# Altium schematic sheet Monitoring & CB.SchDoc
size 431 x 279 mm; Date: Not shown in title block; ApprovedBy: Not shown in title block; CheckedBy: Not shown in title block; Author: Not shown in title block; CompanyName: Not shown in title block; Engineer: Not shown in title block; Organization: Not shown in title block; Address1: Not shown in title block; Address2: Not shown in title block; Address3: Not shown in title block; Address4: Not shown in title block; DocumentNumber: 1; Revision: Use project parameter SCH_Rev; SheetNumber: 2; SheetTotal: 3; PageSetup: Record=PageOptions¦CenterHorizontal=True¦CenterVertical=True¦PrintScale=1.00¦XCorrection=1.00¦YCorrection=1.00¦PrintKind=0¦BorderSize=5000000¦LeftOffset=0¦BottomOffset=0¦Orientation=2¦PaperLength=1000¦PaperWidth=1000¦Scale=100¦PaperSource=15¦PrintQuality=600¦MediaType=1¦DitherType=10¦PaperKind=Letter¦PrintScaleMode=1
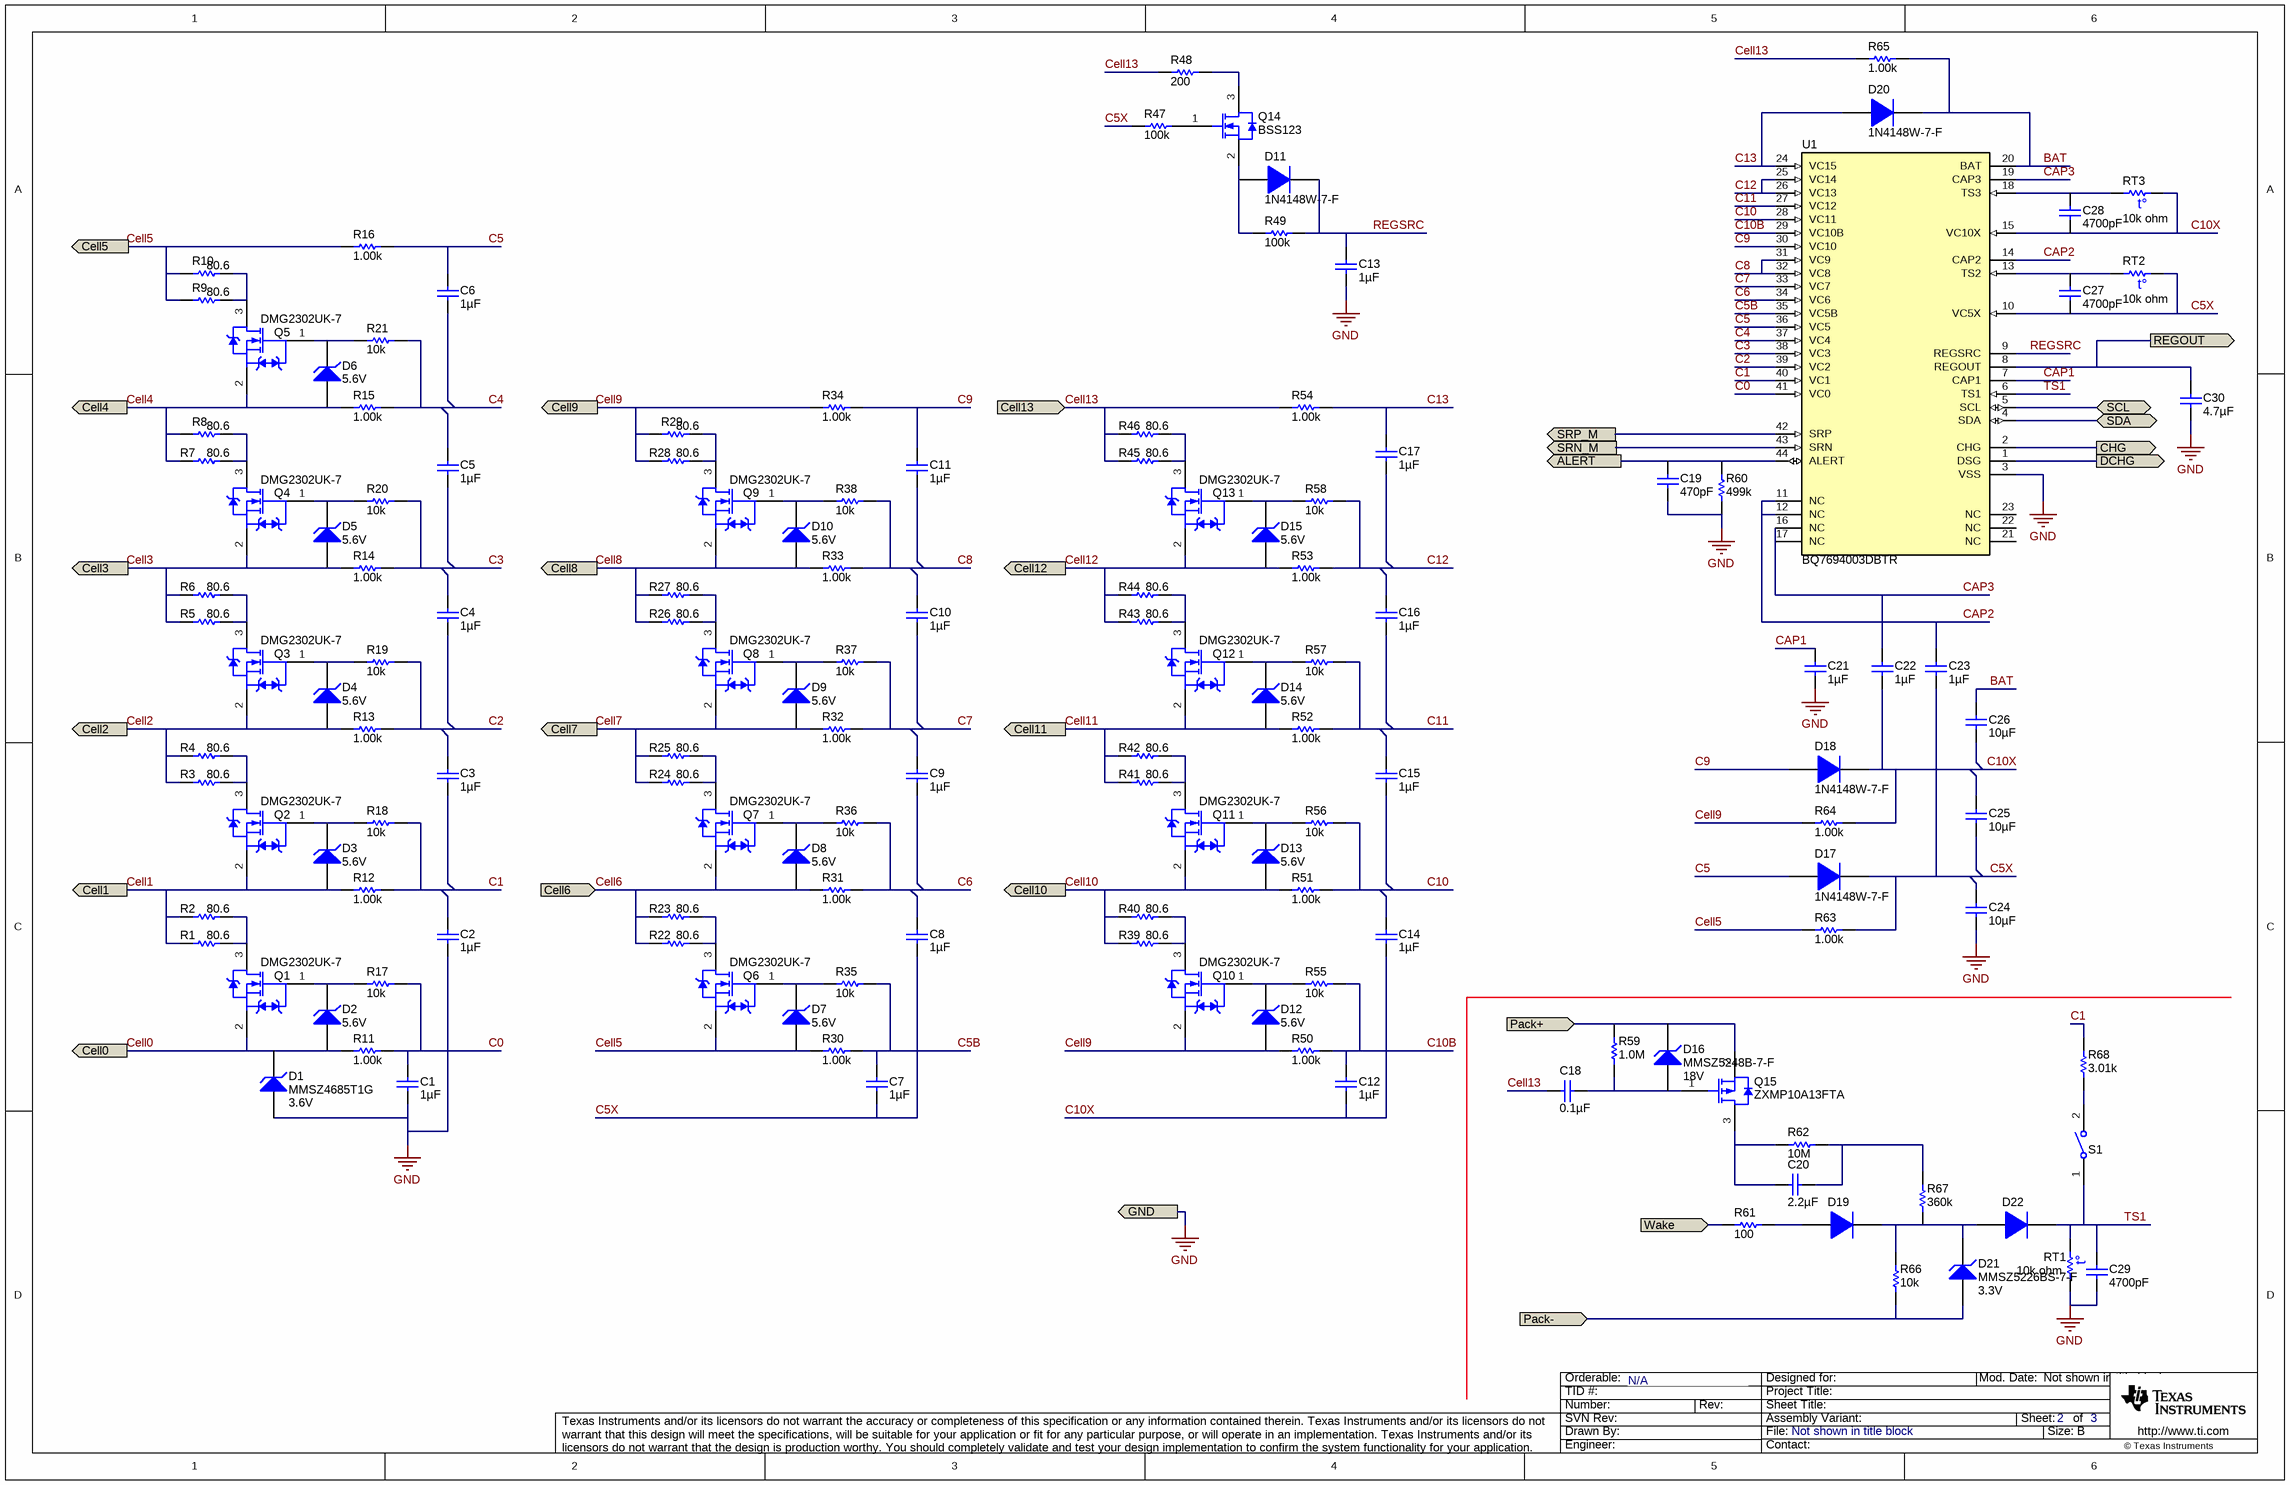
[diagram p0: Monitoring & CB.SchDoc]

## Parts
C1  ValueDisplayed: 1µF  [0603]  (hidden comment: GRM188R71C105KE15D)
C2  ValueDisplayed: 1µF  [0603S]  (hidden comment: GRM188R71C105KE15D)
C3  ValueDisplayed: 1µF  [0603]  (hidden comment: GRM188R71C105KE15D)
C4  ValueDisplayed: 1µF  [0603]  (hidden comment: GRM188R71C105KE15D)
C5  ValueDisplayed: 1µF  [0603]  (hidden comment: GRM188R71C105KE15D)
C6  ValueDisplayed: 1µF  [0603]  (hidden comment: GRM188R71C105KE15D)
C7  ValueDisplayed: 1µF  [0603S]  (hidden comment: GRM188R71C105KE15D)
C8  ValueDisplayed: 1µF  [0603S]  (hidden comment: GRM188R71C105KE15D)
C9  ValueDisplayed: 1µF  [0603]  (hidden comment: GRM188R71C105KE15D)
C10  ValueDisplayed: 1µF  [0603]  (hidden comment: GRM188R71C105KE15D)
C11  ValueDisplayed: 1µF  [0603]  (hidden comment: GRM188R71C105KE15D)
C12  ValueDisplayed: 1µF  [0603]  (hidden comment: GRM188R71C105KE15D)
C13  ValueDisplayed: 1µF  [0603S]  (hidden comment: C1608X7R1V105K080AC)
C14  ValueDisplayed: 1µF  [0603]  (hidden comment: GRM188R71C105KE15D)
C15  ValueDisplayed: 1µF  [0603]  (hidden comment: GRM188R71C105KE15D)
C16  ValueDisplayed: 1µF  [0603]  (hidden comment: GRM188R71C105KE15D)
C17  ValueDisplayed: 1µF  [0603]  (hidden comment: GRM188R71C105KE15D)
C18  ValueDisplayed: 0.1µF  [0805_HV]  (hidden comment: CGA4J2X7R2A104K125AA)
C19  ValueDisplayed: 470pF  [0603]  (hidden comment: GCM1885C1H471JA16D)
C20  ValueDisplayed: 2.2µF  [1210_270]  (hidden comment: GRM32ER72A225KA35L)
C21  ValueDisplayed: 1µF  [0603S]  (hidden comment: GRM188R71C105KE15D)
C22  ValueDisplayed: 1µF  [0603S]  (hidden comment: GRM188R71C105KE15D)
C23  ValueDisplayed: 1µF  [0603S]  (hidden comment: GRM188R71C105KE15D)
C24  ValueDisplayed: 10µF  [1210_280]  (hidden comment: C3225X5R1H106K250AB)
C25  ValueDisplayed: 10µF  [1210_280]  (hidden comment: C3225X5R1H106K250AB)
C26  ValueDisplayed: 10µF  [1210_280]  (hidden comment: C3225X5R1H106K250AB)
C27  ValueDisplayed: 4700pF  [0603S]  (hidden comment: GCM188R71H472KA37D)
C28  ValueDisplayed: 4700pF  [0603]  (hidden comment: GCM188R71H472KA37D)
C29  ValueDisplayed: 4700pF  [0603]  (hidden comment: GCM188R71H472KA37D)
C30  ValueDisplayed: 4.7µF  [0603S]  (hidden comment: GRM188R61C475KAAJ)
D1  MMSZ4685T1G  value 3.6V  [SOD-123]
D2  value 5.6V  [SOD-523]  (hidden comment: BZT52C5V6T-7)
D3  value 5.6V  [SOD-523]  (hidden comment: BZT52C5V6T-7)
D4  value 5.6V  [SOD-523]  (hidden comment: BZT52C5V6T-7)
D5  value 5.6V  [SOD-523]  (hidden comment: BZT52C5V6T-7)
D6  value 5.6V  [SOD-523]  (hidden comment: BZT52C5V6T-7)
D7  value 5.6V  [SOD-523]  (hidden comment: BZT52C5V6T-7)
D8  value 5.6V  [SOD-523]  (hidden comment: BZT52C5V6T-7)
D9  value 5.6V  [SOD-523]  (hidden comment: BZT52C5V6T-7)
D10  value 5.6V  [SOD-523]  (hidden comment: BZT52C5V6T-7)
D11  1N4148W-7-F  [SOD-123]
D12  value 5.6V  [SOD-523]  (hidden comment: BZT52C5V6T-7)
D13  value 5.6V  [SOD-523]  (hidden comment: BZT52C5V6T-7)
D14  value 5.6V  [SOD-523]  (hidden comment: BZT52C5V6T-7)
D15  value 5.6V  [SOD-523]  (hidden comment: BZT52C5V6T-7)
D16  MMSZ5248B-7-F  value 18V  [SOD-123]
D17  1N4148W-7-F  [SOD-123]
D18  1N4148W-7-F  [SOD-123]
D19  SBR0220T5-7  [SOD-523]  (value not drawn)
D20  1N4148W-7-F  [SOD-123]
D21  MMSZ5226BS-7-F  value 3.3V  [SOD-323]
D22  SBR0220T5-7  [SOD-523]  (value not drawn)
Q1  DMG2302UK-7  [SOT-23]
Q2  DMG2302UK-7  [SOT-23]
Q3  DMG2302UK-7  [SOT-23]
Q4  DMG2302UK-7  [SOT-23]
Q5  DMG2302UK-7  [SOT-23]
Q6  DMG2302UK-7  [SOT-23]
Q7  DMG2302UK-7  [SOT-23]
Q8  DMG2302UK-7  [SOT-23]
Q9  DMG2302UK-7  [SOT-23]
Q10  DMG2302UK-7  [SOT-23]
Q11  DMG2302UK-7  [SOT-23]
Q12  DMG2302UK-7  [SOT-23]
Q13  DMG2302UK-7  [SOT-23]
Q14  BSS123  [SOT-23]
Q15  ZXMP10A13FTA  [SOT-23]
R1  ValueDisplayed: 80.6  [1206]  (hidden comment: CRCW120680R6FKEA)
R2  ValueDisplayed: 80.6  [1206]  (hidden comment: CRCW120680R6FKEA)
R3  ValueDisplayed: 80.6  [1206]  (hidden comment: CRCW120680R6FKEA)
R4  ValueDisplayed: 80.6  [1206]  (hidden comment: CRCW120680R6FKEA)
R5  ValueDisplayed: 80.6  [1206]  (hidden comment: CRCW120680R6FKEA)
R6  ValueDisplayed: 80.6  [1206]  (hidden comment: CRCW120680R6FKEA)
R7  ValueDisplayed: 80.6  [1206]  (hidden comment: CRCW120680R6FKEA)
R8  ValueDisplayed: 80.6  [1206]  (hidden comment: CRCW120680R6FKEA)
R9  ValueDisplayed: 80.6  [1206]  (hidden comment: CRCW120680R6FKEA)
R10  ValueDisplayed: 80.6  [1206]  (hidden comment: CRCW120680R6FKEA)
R11  ValueDisplayed: 1.00k  [0603]  (hidden comment: CRCW06031K00FKEA)
R12  ValueDisplayed: 1.00k  [0603]  (hidden comment: CRCW06031K00FKEA)
R13  ValueDisplayed: 1.00k  [0603]  (hidden comment: CRCW06031K00FKEA)
R14  ValueDisplayed: 1.00k  [0603]  (hidden comment: CRCW06031K00FKEA)
R15  ValueDisplayed: 1.00k  [0603]  (hidden comment: CRCW06031K00FKEA)
R16  ValueDisplayed: 1.00k  [0603]  (hidden comment: CRCW06031K00FKEA)
R17  ValueDisplayed: 10k  [0603]  (hidden comment: CRCW060310K0JNEA)
R18  ValueDisplayed: 10k  [0603]  (hidden comment: CRCW060310K0JNEA)
R19  ValueDisplayed: 10k  [0603]  (hidden comment: CRCW060310K0JNEA)
R20  ValueDisplayed: 10k  [0603]  (hidden comment: CRCW060310K0JNEA)
R21  ValueDisplayed: 10k  [0603]  (hidden comment: CRCW060310K0JNEA)
R22  ValueDisplayed: 80.6  [1206]  (hidden comment: CRCW120680R6FKEA)
R23  ValueDisplayed: 80.6  [1206]  (hidden comment: CRCW120680R6FKEA)
R24  ValueDisplayed: 80.6  [1206]  (hidden comment: CRCW120680R6FKEA)
R25  ValueDisplayed: 80.6  [1206]  (hidden comment: CRCW120680R6FKEA)
R26  ValueDisplayed: 80.6  [1206]  (hidden comment: CRCW120680R6FKEA)
R27  ValueDisplayed: 80.6  [1206]  (hidden comment: CRCW120680R6FKEA)
R28  ValueDisplayed: 80.6  [1206]  (hidden comment: CRCW120680R6FKEA)
R29  ValueDisplayed: 80.6  [1206]  (hidden comment: CRCW120680R6FKEA)
R30  ValueDisplayed: 1.00k  [0603]  (hidden comment: CRCW06031K00FKEA)
R31  ValueDisplayed: 1.00k  [0603]  (hidden comment: CRCW06031K00FKEA)
R32  ValueDisplayed: 1.00k  [0603]  (hidden comment: CRCW06031K00FKEA)
R33  ValueDisplayed: 1.00k  [0603]  (hidden comment: CRCW06031K00FKEA)
R34  ValueDisplayed: 1.00k  [0603]  (hidden comment: CRCW06031K00FKEA)
R35  ValueDisplayed: 10k  [0603]  (hidden comment: CRCW060310K0JNEA)
R36  ValueDisplayed: 10k  [0603]  (hidden comment: CRCW060310K0JNEA)
R37  ValueDisplayed: 10k  [0603]  (hidden comment: CRCW060310K0JNEA)
R38  ValueDisplayed: 10k  [0603]  (hidden comment: CRCW060310K0JNEA)
R39  ValueDisplayed: 80.6  [1206]  (hidden comment: CRCW120680R6FKEA)
R40  ValueDisplayed: 80.6  [1206]  (hidden comment: CRCW120680R6FKEA)
R41  ValueDisplayed: 80.6  [1206]  (hidden comment: CRCW120680R6FKEA)
R42  ValueDisplayed: 80.6  [1206]  (hidden comment: CRCW120680R6FKEA)
R43  ValueDisplayed: 80.6  [1206]  (hidden comment: CRCW120680R6FKEA)
R44  ValueDisplayed: 80.6  [1206]  (hidden comment: CRCW120680R6FKEA)
R45  ValueDisplayed: 80.6  [1206]  (hidden comment: CRCW120680R6FKEA)
R46  ValueDisplayed: 80.6  [1206]  (hidden comment: CRCW120680R6FKEA)
R47  ValueDisplayed: 100k  [0603]  (hidden comment: CRCW0603100KFKEA)
R48  ValueDisplayed: 200  [0603]  (hidden comment: CRCW0603200RFKEA)
R49  ValueDisplayed: 100k  [0603]  (hidden comment: CRCW0603100KFKEA)
R50  ValueDisplayed: 1.00k  [0603]  (hidden comment: CRCW06031K00FKEA)
R51  ValueDisplayed: 1.00k  [0603]  (hidden comment: CRCW06031K00FKEA)
R52  ValueDisplayed: 1.00k  [0603]  (hidden comment: CRCW06031K00FKEA)
R53  ValueDisplayed: 1.00k  [0603]  (hidden comment: CRCW06031K00FKEA)
R54  ValueDisplayed: 1.00k  [0603]  (hidden comment: CRCW06031K00FKEA)
R55  ValueDisplayed: 10k  [0603]  (hidden comment: CRCW060310K0JNEA)
R56  ValueDisplayed: 10k  [0603]  (hidden comment: CRCW060310K0JNEA)
R57  ValueDisplayed: 10k  [0603]  (hidden comment: CRCW060310K0JNEA)
R58  ValueDisplayed: 10k  [0603]  (hidden comment: CRCW060310K0JNEA)
R59  ValueDisplayed: 1.0M  [0603]  (hidden comment: CRCW06031M00JNEA)
R60  ValueDisplayed: 499k  [0603]  (hidden comment: CRCW0603499KFKEA)
R61  ValueDisplayed: 100  [0603]  (hidden comment: CRCW0603100RFKEA)
R62  ValueDisplayed: 10M  [0603]  (hidden comment: CRCW060310M0JNEA)
R63  ValueDisplayed: 1.00k  [0603]  (hidden comment: CRCW06031K00FKEA)
R64  ValueDisplayed: 1.00k  [0603]  (hidden comment: CRCW06031K00FKEA)
R65  ValueDisplayed: 1.00k  [0603]  (hidden comment: CRCW06031K00FKEA)
R66  ValueDisplayed: 10k  [0603]  (hidden comment: CRCW060310K0JNEA)
R67  ValueDisplayed: 360k  [0603]  (hidden comment: ERJ-3EKF3603V)
R68  ValueDisplayed: 3.01k  [0603S]  (hidden comment: CRCW06033K01FKEA)
RT1  value 10k ohm  [NTCALUG03]  (hidden comment: NTCALUG03A103G)
RT2  value 10k ohm  [NTCALUG03]  (hidden comment: NTCALUG03A103G)
RT3  value 10k ohm  [NTCALUG03]  (hidden comment: NTCALUG03A103G)
S1  RS-032G05A3-SM RT  [SW_RS-032G05A3-SM]  (value not drawn)
U1  BQ7694003DBTR  [DBT0044A_N]

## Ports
ALERT (out), Cell0 (in), Cell1 (in), Cell2 (in), Cell3 (in), Cell4 (in), Cell5 (in), Cell6 (in), Cell7 (in), Cell8 (in), Cell9 (in), Cell10 (in), Cell11 (in), Cell12 (in), Cell13 (in), CHG (out), DCHG (out), GND, Pack+ (in), Pack- (in), REGOUT (out), SCL (bidir), SDA (bidir), SRN_M (in), SRP_M (in), Wake (in)

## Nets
GND: C1.2 C2.2 C13.2 C19.2 C21.2 C24.1 C29.2 C30.2 D1.2(A) R60.1 RT1.1 U1.3(VSS) ; port GND
ALERT: C19.1 R60.2 U1.44(ALERT) ; port ALERT
BAT: C26.2 D20.1(K) R65.2 U1.20(BAT)
C0: C1.1 R11.2 R17.2 U1.41(VC0)
C1: C2.1 C3.2 R12.2 R18.2 R68.2 U1.40(VC1)
C2: C3.1 C4.2 R13.2 R19.2 U1.39(VC2)
C3: C4.1 C5.2 R14.2 R20.2 U1.38(VC3)
C4: C5.1 C6.2 R15.2 R21.2 U1.37(VC4)
C5: C6.1 D17.2(A) R16.2 U1.36(VC5)
C5B: C7.1 R30.2 R35.2 U1.35(VC5B)
C5X: C7.2 C8.2 C23.2 C24.2 C25.1 C27.2 D17.1(K) R47.1 R63.2 RT2.2 U1.10(VC5X)
C6: C8.1 C9.2 R31.2 R36.2 U1.34(VC6)
C7: C9.1 C10.2 R32.2 R37.2 U1.33(VC7)
C8: C10.1 C11.2 R33.2 R38.2 U1.31(VC9) U1.32(VC8)
C9: C11.1 D18.2(A) R34.2 U1.30(VC10)
C10: C14.1 C15.2 R51.2 R56.2 U1.28(VC11)
C10B: C12.1 R50.2 R55.2 U1.29(VC10B)
C10X: C12.2 C14.2 C22.2 C25.2 C26.1 C28.2 D18.1(K) R64.2 RT3.2 U1.15(VC10X)
C11: C15.1 C16.2 R52.2 R57.2 U1.27(VC12)
C12: C16.1 C17.2 R53.2 R58.2 U1.25(VC14) U1.26(VC13)
C13: C17.1 D20.2(A) R54.2 U1.24(VC15)
CAP1: C21.1 U1.7(CAP1)
CAP2: C23.1 U1.11(NC) U1.12(NC) U1.14(CAP2)
CAP3: C22.1 U1.16(NC) U1.17(NC) U1.19(CAP3)
Cell0: D1.1(K) D2.2(A) Q1.2(S) R11.1 ; port Cell0
Cell1: D3.2(A) Q2.2(S) R1.2 R2.2 R12.1 ; port Cell1
Cell2: D4.2(A) Q3.2(S) R3.2 R4.2 R13.1 ; port Cell2
Cell3: D5.2(A) Q4.2(S) R5.2 R6.2 R14.1 ; port Cell3
Cell4: D6.2(A) Q5.2(S) R7.2 R8.2 R15.1 ; port Cell4
Cell5: D7.2(A) Q6.2(S) R9.2 R10.2 R16.1 R30.1 R63.1 ; port Cell5
Cell6: D8.2(A) Q7.2(S) R22.2 R23.2 R31.1 ; port Cell6
Cell7: D9.2(A) Q8.2(S) R24.2 R25.2 R32.1 ; port Cell7
Cell8: D10.2(A) Q9.2(S) R26.2 R27.2 R33.1 ; port Cell8
Cell9: D12.2(A) Q10.2(S) R28.2 R29.2 R34.1 R50.1 R64.1 ; port Cell9
Cell10: D13.2(A) Q11.2(S) R39.2 R40.2 R51.1 ; port Cell10
Cell11: D14.2(A) Q12.2(S) R41.2 R42.2 R52.1 ; port Cell11
Cell12: D15.2(A) Q13.2(S) R43.2 R44.2 R53.1 ; port Cell12
Cell13: C18.2 R45.2 R46.2 R48.1 R54.1 R65.1 ; port Cell13
CHG: U1.2(CHG) ; port CHG
DCHG: U1.1(DSG) ; port DCHG
Pack+: D16.1(K) Q15.2(S) R59.2 ; port Pack+
Pack-: D21.2(A) R66.1 ; port Pack-
REGOUT: C30.1 U1.8(REGOUT) ; port REGOUT
REGSRC: C13.1 D11.1(K) R49.2 U1.9(REGSRC)
SCL: U1.5(SCL) ; port SCL
SDA: U1.4(SDA) ; port SDA
SRN_M: U1.43(SRN) ; port SRN_M
SRP_M: U1.42(SRP) ; port SRP_M
TS1: C29.1 D22.1(K) RT1.2 S1.1 U1.6(TS1)
Wake: R61.2 ; port Wake
NetC18_1: C18.1 D16.2(A) Q15.1(G) R59.1
NetC20_1: C20.1 R62.2 R67.2
NetC20_2: C20.2 Q15.3(D) R62.1
NetC27_1: C27.1 RT2.1 U1.13(TS2)
NetC28_1: C28.1 RT3.1 U1.18(TS3)
NetD2_1: D2.1(K) Q1.1(G) R17.1
NetD3_1: D3.1(K) Q2.1(G) R18.1
NetD4_1: D4.1(K) Q3.1(G) R19.1
NetD5_1: D5.1(K) Q4.1(G) R20.1
NetD6_1: D6.1(K) Q5.1(G) R21.1
NetD7_1: D7.1(K) Q6.1(G) R35.1
NetD8_1: D8.1(K) Q7.1(G) R36.1
NetD9_1: D9.1(K) Q8.1(G) R37.1
NetD10_1: D10.1(K) Q9.1(G) R38.1
NetD11_2: D11.2(A) Q14.2(S) R49.1
NetD12_1: D12.1(K) Q10.1(G) R55.1
NetD13_1: D13.1(K) Q11.1(G) R56.1
NetD14_1: D14.1(K) Q12.1(G) R57.1
NetD15_1: D15.1(K) Q13.1(G) R58.1
NetD19_1: D19.1(K) D21.1(K) D22.2(A) R66.2 R67.1
NetD19_2: D19.2(A) R61.1
NetQ1_3: Q1.3(D) R1.1 R2.1
NetQ2_3: Q2.3(D) R3.1 R4.1
NetQ3_3: Q3.3(D) R5.1 R6.1
NetQ4_3: Q4.3(D) R7.1 R8.1
NetQ5_3: Q5.3(D) R9.1 R10.1
NetQ6_3: Q6.3(D) R22.1 R23.1
NetQ7_3: Q7.3(D) R24.1 R25.1
NetQ8_3: Q8.3(D) R26.1 R27.1
NetQ9_3: Q9.3(D) R28.1 R29.1
NetQ10_3: Q10.3(D) R39.1 R40.1
NetQ11_3: Q11.3(D) R41.1 R42.1
NetQ12_3: Q12.3(D) R43.1 R44.1
NetQ13_3: Q13.3(D) R45.1 R46.1
NetQ14_1: Q14.1(G) R47.2
NetQ14_3: Q14.3(D) R48.2
NetR68_1: R68.1 S1.2

Not connected (* = marked no-connect by the designer): U1 21(NC) 22(NC) 23(NC)

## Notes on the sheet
- N/A

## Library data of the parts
C1 C3-C6 C9-C12 C14-C17 = GRM188R71C105KE15D: CAP, CERM, 1 µF, 16 V,+/- 10%, X7R, 0603; Manufacturer: MuRata; Polarized: N; CompType: Capacitor; Value: 1uF; U/M: EA; Cap_F: 0.000001; Tolerance_%: 10; VDC_V: 16; Value2: 16V; TaMin_C: -55; TaMax_C: 125; SizeArea_mm2: 1.28; SizeAreaWB_mm2: 4.68; SizeX_mm: 1.6; SizeY_mm: 0.8; SizeZ_mm: 1; AEC Category: Q200
C2 C7 C8 C21-C23 = GRM188R71C105KE15D: CAP, CERM, 1 µF, 16 V,+/- 10%, X7R, 0603; Manufacturer: MuRata; Polarized: N; CompType: Capacitor; Value: 1uF; U/M: EA; Cap_F: 0.000001; Tolerance_%: 10; VDC_V: 16; Value2: 16V; TaMin_C: -55; TaMax_C: 125; Cap_Case: 0603; SizeArea_mm2: 1.28; SizeAreaWB_mm2: 4.68; SizeX_mm: 1.6; SizeY_mm: 0.8; SizeZ_mm: 1; AEC Category: Q200
C13 = C1608X7R1V105K080AC: CAP, CERM, 1 µF, 35 V,+/- 10%, X7R, 0603; Manufacturer: TDK; Polarized: N; CompType: Capacitor; Value: 1uF; U/M: EA; Cap_F: 0.000001; Tolerance_%: 10; VDC_V: 35; Value2: 35V; TaMin_C: -55; TaMax_C: 125; Cap_Case: 0603; SizeArea_mm2: 1.28; SizeAreaWB_mm2: 4.68; SizeX_mm: 1.6; SizeY_mm: 0.8; SizeZ_mm: 1; AEC Category: Q200; Green_Lifecycle: Active; Green_REACh: Passed
C18 = CGA4J2X7R2A104K125AA: CAP, CERM, 0.1 µF, 100 V,+/- 10%, X7R, AEC-Q200 Grade 1, 0805; Manufacturer: TDK; Polarized: N; CompType: Capacitor; Value: 0.1uF; U/M: EA; Cap_F: 0.0000001; Tolerance_%: 10; ESR_ohm: 0.020726; Value1: 0.020726 ohm; VDC_V: 100; Value2: 100V; IRMS_A: 1.456; TaMin_C: -55; TaMax_C: 125; Cap_Case: 0805; SizeArea_mm2: 2.5; SizeAreaWB_mm2: 6.75; SizeX_mm: 2; SizeY_mm: 1.25; SizeZ_mm: 1.45; AEC Category: Q200; AEC Qualified: Y; AEC Grade: 1; Green_Lifecycle: Active; Green_REACh: Passed
C19 = GCM1885C1H471JA16D: CAP, CERM, 470 pF, 50 V,+/- 5%, C0G/NP0, AEC-Q200 Grade 1, 0603; Manufacturer: MuRata; Polarized: N; CompType: Capacitor; Value: 470pF; U/M: EA; Cap_F: 0.00000000047; Tolerance_%: 5; VDC_V: 50; Value2: 50V; TaMin_C: -55; TaMax_C: 125; SizeArea_mm2: 1.28; SizeAreaWB_mm2: 4.68; SizeX_mm: 1.6; SizeY_mm: 0.8; SizeZ_mm: 1; AEC Category: Q200; AEC Qualified: Y; Green_Lifecycle: Active; Green_REACh: Passed
C20 = GRM32ER72A225KA35L: CAP, CERM, 2.2 µF, 100 V,+/- 10%, X7R, 1210; Manufacturer: MuRata; Polarized: N; CompType: Capacitor; Value: 2.2uF; U/M: EA; Cap_F: 0.0000022; Tolerance_%: 10; ESR_ohm: 0.007; Value1: 0.007 ohm; VDC_V: 100; Value2: 100V; IRMS_A: 4.4; TaMin_C: -55; TaMax_C: 125; Cap_Case: 1210; SizeArea_mm2: 8; SizeAreaWB_mm2: 14.7; SizeX_mm: 3.2; SizeY_mm: 2.5; SizeZ_mm: 2.7; AEC Category: Q200; Green_Lifecycle: Active; Green_REACh: Passed
C24-C26 = C3225X5R1H106K250AB: CAP, CERM, 10 µF, 50 V,+/- 10%, X5R, 1210; Manufacturer: TDK; Polarized: N; CompType: Capacitor; Value: 10uF; U/M: EA; Cap_F: 0.00001; Tolerance_%: 10; VDC_V: 50; Value2: 50V; TaMin_C: -55; TaMax_C: 85; Cap_Case: 1210; SizeArea_mm2: 8; SizeAreaWB_mm2: 14.7; SizeX_mm: 3.2; SizeY_mm: 2.5; SizeZ_mm: 2.8; AEC Category: Q200; Green_Lifecycle: Active; Green_REACh: Passed
C27 = GCM188R71H472KA37D: CAP, CERM, 4700 pF, 50 V,+/- 10%, X7R, AEC-Q200 Grade 1, 0603; Manufacturer: MuRata; Polarized: N; CompType: Capacitor; Value: 4700pF; U/M: EA; Cap_F: 0.0000000047; Tolerance_%: 10; VDC_V: 50; Value2: 50V; TaMin_C: -55; TaMax_C: 125; Cap_Case: 0603; SizeArea_mm2: 1.28; SizeAreaWB_mm2: 4.68; SizeX_mm: 1.6; SizeY_mm: 0.8; SizeZ_mm: 1; AEC Category: Q200; AEC Qualified: Y
C28 C29 = GCM188R71H472KA37D: CAP, CERM, 4700 pF, 50 V,+/- 10%, X7R, AEC-Q200 Grade 1, 0603; Manufacturer: MuRata; Polarized: N; CompType: Capacitor; Value: 4700pF; U/M: EA; Cap_F: 0.0000000047; Tolerance_%: 10; VDC_V: 50; Value2: 50V; TaMin_C: -55; TaMax_C: 125; SizeArea_mm2: 1.28; SizeAreaWB_mm2: 4.68; SizeX_mm: 1.6; SizeY_mm: 0.8; SizeZ_mm: 1; AEC Category: Q200; AEC Qualified: Y
C30 = GRM188R61C475KAAJ: CAP, CERM, 4.7 µF, 16 V,+/- 10%, X5R, 0603; Manufacturer: MuRata; Polarized: N; CompType: Capacitor; Value: 4.7uF; U/M: EA; Cap_F: 0.0000047; Tolerance_%: 10; VDC_V: 16; Value2: 16V; TaMin_C: -55; TaMax_C: 85; Cap_Case: 0603; SizeArea_mm2: 1.28; SizeAreaWB_mm2: 4.68; SizeX_mm: 1.6; SizeY_mm: 0.8; SizeZ_mm: 1; AEC Category: Q200; Green_Lifecycle: Active; Green_REACh: Passed
D1 = MMSZ4685T1G: Diode, Zener, 3.6 V, 500 mW, SOD-123; Manufacturer: ON Semiconductor; SymbolCreator: a0412235; U/M: EA; Power_W: 0.5; Vz_V: 3.6; Value1: 0.5W; RJA_CperW: 340; SizeAreaWB_mm2: 13.095; SizeArea_mm2: 6.545; SizeX_mm: 3.85; SizeY_mm: 1.7; SizeZ_mm: 1.35; AEC Category: Q101; Green_Lifecycle: Active; Green_REACh: Passed
D2-D10 D12-D15 = BZT52C5V6T-7: Diode, Zener, 5.6 V, 300 mW, SOD-523; Manufacturer: Diodes Inc.; SymbolCreator: a0412235; U/M: EA; Power_W: 0.3; Vz_V: 5.6; Value1: 0.3W; RJA_CperW: 417; SizeAreaWB_mm2: 5.13; SizeArea_mm2: 1.53; SizeX_mm: 1.7; SizeY_mm: 0.9; SizeZ_mm: 0.65; AEC Category: Q101; Green_Lifecycle: Active; Green_REACh: Passed
D11 D17 D18 D20 = 1N4148W-7-F: Diode, Ultrafast, 100 V, 0.15 A, SOD-123; Manufacturer: Diodes Inc.; U/M: EA; Vf_V: 1.25; Value: 100V; Value1: 0.15A; Value2: 1.25V; Io_A: 0.15; Vr_V: 100; TJmax_C: 150; SizeAreaWB_mm2: 13.095; SizeArea_mm2: 6.545; SizeX_mm: 3.85; SizeY_mm: 1.7; SizeZ_mm: 1.35; AEC Category: Q101; Green_Lifecycle: Active; Green_REACh: Passed
D16 = MMSZ5248B-7-F: Diode, Zener, 18 V, 500 mW, SOD-123; Manufacturer: Diodes Inc.; SymbolCreator: a0412235; U/M: EA; Power_W: 0.5; Vz_V: 18; Value1: 0.5W; RJA_CperW: 350; SizeAreaWB_mm2: 13.095; SizeArea_mm2: 6.545; SizeX_mm: 3.85; SizeY_mm: 1.7; SizeZ_mm: 1.35; AEC Category: Q101; Green_Lifecycle: Active; Green_REACh: Passed
D19 D22 = SBR0220T5-7: Diode, Super Barrier Rectifier, 20 V, 0.2 A, SOD-523; Manufacturer: Diodes Inc.; U/M: EA; Vf_V: 0.43; Value: 20V; Value1: 0.2A; Value2: 0.43V; Io_A: 0.2; Vr_V: 20; TJmax_C: 150; SizeAreaWB_mm2: 5.13; SizeArea_mm2: 1.53; SizeX_mm: 1.7; SizeY_mm: 0.9; SizeZ_mm: 0.65; AEC Category: Q101; Green_Lifecycle: Active; Green_REACh: Passed
D21 = MMSZ5226BS-7-F: Diode, Zener, 3.3 V, 200 mW, SOD-323; Manufacturer: Diodes Inc.; SymbolCreator: a0412235; U/M: EA; Power_W: 0.2; Vz_V: 3.3; Value1: 0.2W; RJA_CperW: 350; SizeAreaWB_mm2: 8.695; SizeArea_mm2: 3.645; SizeX_mm: 2.7; SizeY_mm: 1.35; SizeZ_mm: 1; AEC Category: Q101; Green_Lifecycle: Active; Green_REACh: Passed
Q1-Q13 = DMG2302UK-7: MOSFET, N-CH, 20 V, 2.8 A, AEC-Q101, SOT-23; Manufacturer: Diodes Inc.; Alternate Manufacturer: None; SymbolCreator: x0208325; U/M: EA; ChType: N; Value: 20V; VdsMax_V: 20; Value1: 0.09 ohm; Rdson45_ohm: 0.09; Value2: 1.4 nC; QgTyp_nC: 1.4; Vgs_V: 12; IdsMax_A: 2.8; SizeAreaWB_mm2: 14; SizeArea_mm2: 7.5; SizeX_mm: 2.5; SizeY_mm: 3; SizeZ_mm: 1.1; AEC Category: Q101; AEC Qualified: Y; Green_Lifecycle: Active; Green_REACh: Passed
Q14 = BSS123: MOSFET, N-CH, 100 V, 0.17 A, SOT-23; Manufacturer: Fairchild Semiconductor; Alternate Manufacturer: None; U/M: EA; ChType: N; Value: 100V; VdsMax_V: 100; Value1: 10 ohm; Rdson45_ohm: 10; Value2: 1.8 nC; QgTyp_nC: 1.8; Vgs_V: 20; IdsMax_A: 0.17; SizeAreaWB_mm2: 14; SizeArea_mm2: 7.5; SizeX_mm: 2.5; SizeY_mm: 3; SizeZ_mm: 1.1; AEC Category: Q101; Green_Lifecycle: Active; Green_REACh: Passed
Q15 = ZXMP10A13FTA: MOSFET, P-CH, -100 V, -0.6 A, SOT-23; Manufacturer: Diodes Inc.; Alternate Manufacturer: None; U/M: EA; ChType: P; Value: -100V; Value1: 1 ohm; Rdson45_ohm: 1; Value2: 3.5 nC; QgTyp_nC: 3.5; Vgs_V: -4; SizeAreaWB_mm2: 14; SizeArea_mm2: 7.5; SizeX_mm: 2.5; SizeY_mm: 3; SizeZ_mm: 1.1; AEC Category: Q101; Green_Lifecycle: Active; Green_REACh: Passed
R1-R10 R22-R29 R39-R46 = CRCW120680R6FKEA: RES, 80.6, 1%, 0.25 W, 1206; Manufacturer: Vishay-Dale; CompType: Resistor; Value: 80.6; Value_Code: 80R6; Tolerance_%: 1; Power_W: 0.25; Value2: 0.25W; VDC_V: 200; TempCo: 100 ppm/C; SizeArea_mm2: 5.12; SizeX_mm: 3.2; SizeY_mm: 1.6; SizeZ_mm: 1.35; EIA_Code: E96; U/M: EA; AEC Category: Q200
R11-R16 R30-R34 R50-R54 R63-R65 = CRCW06031K00FKEA: RES, 1.00 k, 1%, 0.1 W, 0603; Manufacturer: Vishay-Dale; CompType: Resistor; Value: 1.00k; Res_ohm: 1000; Value_Code: 1k00; Tolerance_%: 1; Power_W: 0.1; Value2: 0.1W; VDC_V: 75; TempCo: 100 ppm/C; SizeArea_mm2: 1.28; SizeX_mm: 1.6; SizeY_mm: 0.8; EIA_Code: E96; U/M: EA; AEC Category: Q200; Green_Lifecycle: Active; Green_REACh: Passed
R17-R21 R35-R38 R55-R58 R66 = CRCW060310K0JNEA: RES, 10 k, 5%, 0.1 W, 0603; Manufacturer: Vishay-Dale; CompType: Resistor; Value: 10k; Res_ohm: 10000; Value_Code: 10k0; Tolerance_%: 5; Power_W: 0.1; Value2: 0.1W; VDC_V: 75; TempCo: 200 ppm/C; SizeArea_mm2: 1.28; SizeX_mm: 1.6; SizeY_mm: 0.8; SizeZ_mm: 1; EIA_Code: E24; U/M: EA; AEC Category: Q200; Green_Lifecycle: Active; Green_REACh: Passed
R47 R49 = CRCW0603100KFKEA: RES, 100 k, 1%, 0.1 W, 0603; Manufacturer: Vishay-Dale; CompType: Resistor; Value: 100k; Res_ohm: 100000; Tolerance_%: 1; Power_W: 0.1; Value2: 0.1W; VDC_V: 75; TempCo: 100 ppm/C; SizeArea_mm2: 1.28; SizeX_mm: 1.6; SizeY_mm: 0.8; EIA_Code: E96; U/M: EA; AEC Category: Q200; Green_Lifecycle: Active; Green_REACh: Passed
R48 = CRCW0603200RFKEA: RES, 200, 1%, 0.1 W, 0603; Manufacturer: Vishay-Dale; CompType: Resistor; Value: 200; Value_Code: 200R; Tolerance_%: 1; Power_W: 0.1; Value2: 0.1W; VDC_V: 75; TempCo: 100 ppm/C; SizeArea_mm2: 1.28; SizeX_mm: 1.6; SizeY_mm: 0.8; EIA_Code: E96; U/M: EA; AEC Category: Q200; Green_Lifecycle: Active; Green_REACh: Passed
R59 = CRCW06031M00JNEA: RES, 1.0 M, 5%, 0.1 W, 0603; Manufacturer: Vishay-Dale; CompType: Resistor; Value: 1.0Meg; Res_ohm: 1000000; Value_Code: 1M00; Tolerance_%: 5; Power_W: 0.1; Value2: 0.1W; VDC_V: 75; TempCo: 200 ppm/C; SizeArea_mm2: 1.28; SizeX_mm: 1.6; SizeY_mm: 0.8; SizeZ_mm: 1; EIA_Code: E24; U/M: EA; AEC Category: Q200; Green_Lifecycle: Active; Green_REACh: Passed
R60 = CRCW0603499KFKEA: RES, 499 k, 1%, 0.1 W, 0603; Manufacturer: Vishay-Dale; CompType: Resistor; Value: 499k; Res_ohm: 499000; Tolerance_%: 1; Power_W: 0.1; Value2: 0.1W; VDC_V: 75; TempCo: 100 ppm/C; SizeArea_mm2: 1.28; SizeX_mm: 1.6; SizeY_mm: 0.8; EIA_Code: E96; U/M: EA; AEC Category: Q200; Green_Lifecycle: Active; Green_REACh: Passed
R61 = CRCW0603100RFKEA: RES, 100, 1%, 0.1 W, 0603; Manufacturer: Vishay-Dale; CompType: Resistor; Value: 100; Value_Code: 100R; Tolerance_%: 1; Power_W: 0.1; Value2: 0.1W; VDC_V: 75; TempCo: 100 ppm/C; SizeArea_mm2: 1.28; SizeX_mm: 1.6; SizeY_mm: 0.8; EIA_Code: E96; U/M: EA; AEC Category: Q200; Green_Lifecycle: Active; Green_REACh: Passed
R62 = CRCW060310M0JNEA: RES, 10 M, 5%, 0.1 W, 0603; Manufacturer: Vishay-Dale; CompType: Resistor; Value: 10Meg; Res_ohm: 10000000; Value_Code: 10M0; Tolerance_%: 5; Power_W: 0.1; Value2: 0.1W; VDC_V: 75; TempCo: 200 ppm/C; SizeArea_mm2: 1.28; SizeX_mm: 1.6; SizeY_mm: 0.8; SizeZ_mm: 1; EIA_Code: E24; U/M: EA; AEC Category: Q200; Green_Lifecycle: Active; Green_REACh: Passed
R67 = ERJ-3EKF3603V: RES, 360 k, 1%, 0.1 W, AEC-Q200 Grade 0, 0603; Manufacturer: Panasonic; CompType: Resistor; Value: 360k; Res_ohm: 360000; Tolerance_%: 1; Power_W: 0.1; Value2: 0.1W; VDC_V: 75; TempCo: 100 ppm/C; SizeArea_mm2: 1.28; SizeX_mm: 1.6; SizeY_mm: 0.8; U/M: EA; AEC Category: Q200; AEC Qualified: Y; AEC Grade: 0; Green_Lifecycle: Active; Green_REACh: Passed
R68 = CRCW06033K01FKEA: RES, 3.01 k, 1%, 0.1 W, 0603; Manufacturer: Vishay-Dale; CompType: Resistor; Value: 3.01k; Res_ohm: 3010; Value_Code: 3k01; Tolerance_%: 1; Power_W: 0.1; Value2: 0.1W; VDC_V: 75; TempCo: 100 ppm/C; SizeArea_mm2: 1.28; SizeX_mm: 1.6; SizeY_mm: 0.8; EIA_Code: E96; U/M: EA; AEC Category: Q200; Green_Lifecycle: Active; Green_REACh: Passed
RT1-RT3 = NTCALUG03A103G: Thermistor NTC, 10k ohm, 2%, NTC Thermistor, Mini Lug Sensor, Pitch 1.5mm; Manufacturer: Vishay-Bccomponents; Tolerance_%: 2; Power_W: 0.1; TaMin_C: -40; TaMax_C: 125; U/M: EA
S1 = RS-032G05A3-SM RT: Switch, Tactile, SPST-NO, 0.05A, 12V, SMD; Manufacturer: C&K Components; SymbolCreator: a0799628; VDC_V: 12; SwitchFunction: Off-Mom; PositionCount: 1; CurrentRating_mA: 50; Green_Lifecycle: Not Set; Green_REACh: Incomplete
U1 = CMP-0065910-1: 9 to 15-Series Cell Li-Ion and Li-Phosphate Battery Monitor (bq76940 Family), DBT0044A (TSSOP-44); Alternate Manufacturer: Texas Instruments; SizeAreaWB_mm2: 109.2; U/M: EA; SizeZ_mm: 1.2; SizeX_mm: 6.4; SizeY_mm: 11.0; SizeArea_mm2: 70.4; CompType: IC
